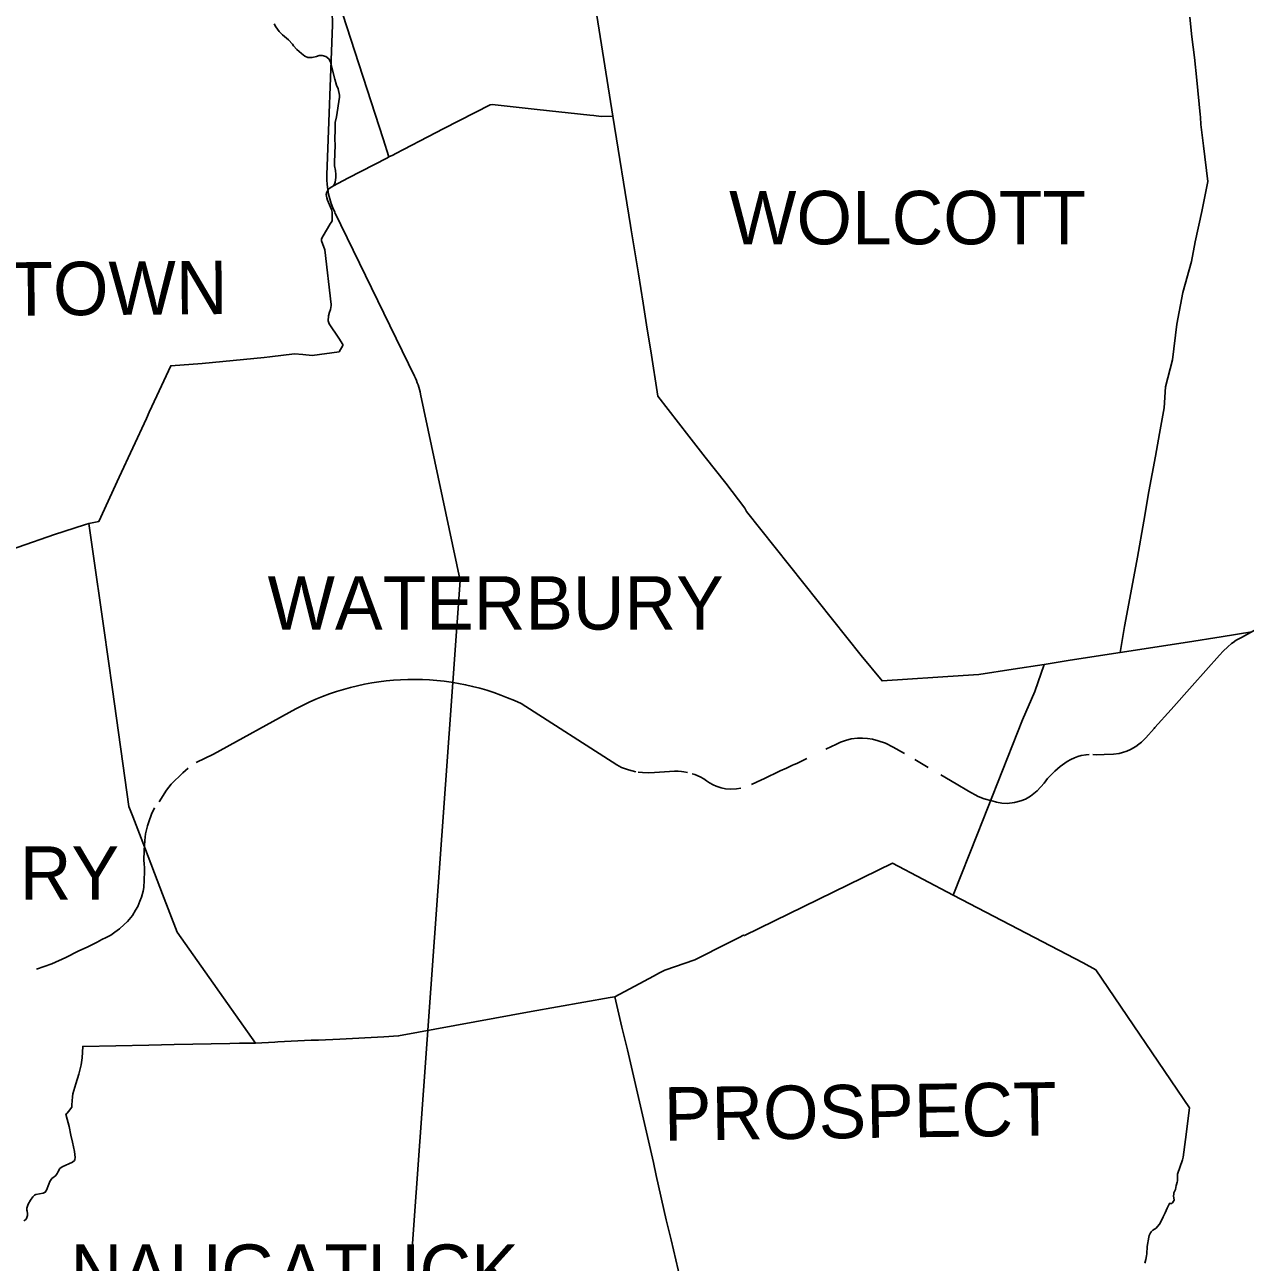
# Model space of a CAD drawing. Extents: x 0 to 2603, y -226 to 830.
# Drawn here: x 129.76 to 160.62, y 575 to 606.28 of the extents above; entities that cross this region are included whole.
import ezdxf

# ---------------------------------------------------------------- set-up
doc = ezdxf.new("R2010")
doc.units = 0
for name, color, linetype in [('CT_TSH_Map_Districts', 7, 'Continuous'), ('CT_TSH_Map_Interstate_Roads', 7, 'Continuous'), ('CT_TSH_Map_Town_Limits', 7, 'Continuous'), ('CT_TSH_Map_Town_Text', 7, 'Continuous'), ('CT_TSH_Map_US_and_State_Routes', 7, 'Continuous')]:
    doc.layers.add(name, color=color, linetype=linetype)

msp = doc.modelspace()

# ---------------------------------------------------------------- linework, layer by layer
at = {"layer": 'CT_TSH_Map_Districts'}
for points in [[(150.903, 609.889), (148.007, 607.903), (147.918, 607.835), (147.204, 607.367), (144.141, 607.01), (144.225, 606.511), (144.636, 603.968)], [(144.636, 603.968), (145.083, 601.204), (145.095, 601.095), (145.206, 600.434), (145.279, 599.977), (145.399, 599.241), (145.5, 598.58), (145.591, 598.037), (145.771, 596.887), (146.558, 595.88), (146.971, 595.343), (147.486, 594.686), (147.968, 594.058), (148.013, 593.97), (150.911, 590.334), (151.44, 589.692), (153.488, 589.831), (153.888, 589.851), (154.755, 589.988), (155.542, 590.106)], [(153.236, 584.273), (153.851, 585.821), (154.988, 588.704), (155.3, 589.426), (155.542, 590.106)], [(158.083, 574.97), (158.112, 575.066), (158.125, 575.154), (158.139, 575.205), (158.143, 575.393), (158.185, 575.631), (158.194, 575.671), (158.225, 575.736), (158.246, 575.763), (158.285, 575.803), (158.371, 575.857), (158.406, 575.901), (158.454, 575.962), (158.505, 576.051), (158.546, 576.145), (158.564, 576.177), (158.597, 576.249), (158.654, 576.362), (158.707, 576.482), (158.763, 576.484), (158.785, 576.498), (158.813, 576.54), (158.823, 576.564), (158.811, 576.676), (158.815, 576.717), (158.822, 576.753), (158.859, 576.838), (158.881, 576.933), (158.886, 576.964), (158.905, 577.02), (158.912, 577.054), (158.913, 577.151), (158.915, 577.219), (159.04, 577.585), (159.054, 577.65), (159.117, 578.102), (159.211, 578.896), (156.85, 582.386), (156.526, 582.564), (153.236, 584.273)]]:
    msp.add_lwpolyline(points, dxfattribs=at)
at = {"layer": 'CT_TSH_Map_Interstate_Roads'}
for points in [[(161.288, 591.209), (160.837, 590.96), (160.526, 590.791), (160.396, 590.717), (160.317, 590.663), (160.276, 590.633), (160.181, 590.55), (160.068, 590.439), (159.974, 590.34), (159.284, 589.568), (158.749, 588.969), (158.338, 588.511), (158.321, 588.489), (158.108, 588.253), (158.005, 588.145), (157.935, 588.088), (157.858, 588.034)], [(145.212, 587.395), (145.025, 587.441), (144.855, 587.506), (144.735, 587.569), (142.314, 589.116)], [(136.614, 588.984), (134.533, 587.841), (134.097, 587.632)], [(151.724, 588.015), (151.524, 588.114), (151.345, 588.179), (151.195, 588.215), (151.073, 588.235), (150.946, 588.244), (150.82, 588.244), (150.66, 588.223), (150.512, 588.183), (150.391, 588.142), (150.268, 588.085), (150.164, 588.03), (150.016, 587.965)], [(152.011, 587.854), (151.724, 588.015)], [(156.478, 587.801), (156.394, 587.782), (156.306, 587.749), (156.212, 587.707), (156.117, 587.652), (155.94, 587.523), (155.812, 587.409), (155.623, 587.225), (155.541, 587.109)], [(156.68, 587.829), (156.599, 587.824), (156.478, 587.801)], [(156.867, 587.822), (156.773, 587.83)], [(157.724, 587.957), (157.632, 587.915), (157.522, 587.88), (157.437, 587.858), (157.296, 587.839), (157.056, 587.827), (156.867, 587.822)], [(157.858, 588.034), (157.724, 587.957)], [(133.893, 587.482), (133.762, 587.367), (133.464, 587.077), (133.348, 586.927), (133.162, 586.637)], [(149.214, 587.575), (149.176, 587.563), (149.023, 587.488), (148.863, 587.421), (148.454, 587.219)], [(149.535, 587.731), (149.52, 587.724), (149.288, 587.605), (149.214, 587.575)], [(152.609, 587.502), (152.27, 587.7)], [(146.429, 587.391), (146.367, 587.4), (146.283, 587.405), (146.191, 587.406), (146.066, 587.401), (145.813, 587.387), (145.69, 587.375), (145.531, 587.37), (145.383, 587.376), (145.269, 587.386)], [(146.52, 587.372), (146.429, 587.391)], [(147.868, 586.983), (147.758, 586.962), (147.601, 586.955), (147.483, 586.963), (147.368, 586.986), (147.247, 587.028), (147.166, 587.064), (147.076, 587.113), (146.998, 587.162), (146.931, 587.216), (146.84, 587.266), (146.705, 587.322), (146.635, 587.343)], [(148.454, 587.219), (148.39, 587.188), (148.135, 587.071)], [(154.215, 586.657), (154.025, 586.706), (153.87, 586.765), (153.627, 586.901), (153.316, 587.086), (152.923, 587.317)], [(155.541, 587.109), (155.365, 586.909), (155.193, 586.775), (155.067, 586.704), (154.949, 586.659), (154.789, 586.617), (154.607, 586.595), (154.466, 586.602), (154.338, 586.624), (154.227, 586.656)], [(133.038, 586.482), (132.967, 586.324), (132.897, 586.128), (132.862, 586.026), (132.816, 585.821), (132.8, 585.66)], [(132.8, 585.66), (132.778, 585.402), (132.774, 585.158), (132.778, 585.064), (132.79, 584.963), (132.788, 584.871), (132.78, 584.652), (132.774, 584.469), (132.755, 584.375), (132.715, 584.228), (132.673, 584.127)], [(132.673, 584.127), (132.617, 583.986), (132.559, 583.892), (132.485, 583.764), (132.359, 583.606), (132.275, 583.532), (132.16, 583.426), (132.043, 583.339), (131.937, 583.263), (131.822, 583.204), (131.713, 583.152)], [(131.713, 583.152), (131.594, 583.09), (131.357, 582.966), (131.112, 582.858), (130.801, 582.7), (130.444, 582.542), (130.06, 582.403)]]:
    msp.add_lwpolyline(points, dxfattribs=at)
msp.add_arc((139.595, 583.395), 6.334, 64.576, 118.0692, dxfattribs=at)
at = {"layer": 'CT_TSH_Map_Town_Limits'}
for points in [[(138.331, 626.019), (137.723, 621.006), (137.355, 617.881), (137.077, 615.36), (136.757, 612.369), (136.636, 611.187), (136.553, 610.437), (136.656, 610.108), (136.665, 610.067), (137.111, 608.697), (137.489, 607.518), (137.807, 606.532), (138.825, 603.397), (138.97, 602.938)], [(150.903, 609.889), (148.007, 607.903), (147.918, 607.835), (147.204, 607.367), (144.141, 607.01), (144.225, 606.511), (144.636, 603.968)], [(136.067, 606.298), (136.11, 606.227), (136.196, 606.109), (136.275, 606.021), (136.428, 605.895), (136.533, 605.786), (136.556, 605.745), (136.642, 605.654), (136.758, 605.552), (136.846, 605.486), (136.918, 605.452), (136.957, 605.447), (137.03, 605.451), (137.139, 605.476), (137.208, 605.498), (137.286, 605.501), (137.372, 605.475), (137.411, 605.449), (137.458, 605.403), (137.496, 605.329), (137.599, 604.904), (137.646, 604.748), (137.684, 604.655), (137.722, 604.499), (137.721, 604.443), (137.642, 603.949), (137.614, 603.804), (137.608, 603.634), (137.603, 603.378), (137.609, 603.239), (137.591, 602.799), (137.597, 602.71), (137.623, 602.595), (137.63, 602.495), (137.626, 602.414), (137.612, 602.294), (137.584, 602.234), (137.567, 602.208)], [(159.224, 606.47), (159.277, 605.972), (159.339, 605.445), (159.397, 604.872), (159.481, 604.01), (159.493, 603.942), (159.505, 603.759), (159.572, 603.216), (159.676, 602.312), (159.525, 601.555), (159.36, 600.787), (159.267, 600.291), (159.043, 599.505), (158.897, 598.707), (158.787, 597.809), (158.606, 597.123), (158.577, 596.594), (158.454, 595.946), (158.351, 595.375), (158.188, 594.477), (158.058, 593.728), (157.899, 592.82), (157.706, 591.784), (157.573, 591.065), (157.462, 590.407)], [(144.636, 603.968), (144.338, 603.96), (144.154, 603.98), (144.052, 603.989), (142.718, 604.133), (142.647, 604.14), (141.584, 604.26), (141.527, 604.256), (140.355, 603.651), (139.953, 603.444), (139.338, 603.126), (139.145, 603.026), (139.071, 602.983), (138.97, 602.938)], [(144.636, 603.968), (145.083, 601.204), (145.095, 601.095), (145.206, 600.434), (145.279, 599.977), (145.399, 599.241), (145.5, 598.58), (145.591, 598.037), (145.771, 596.887), (146.558, 595.88), (146.971, 595.343), (147.486, 594.686), (147.968, 594.058), (148.013, 593.97), (150.911, 590.334), (151.44, 589.692), (153.488, 589.831), (153.888, 589.851), (154.755, 589.988), (155.542, 590.106)], [(137.567, 602.208), (137.935, 602.397), (138.934, 602.914), (138.97, 602.938)], [(131.381, 593.671), (131.638, 593.721), (132.149, 594.841), (132.838, 596.326), (132.908, 596.488), (133.104, 596.898), (133.453, 597.657), (134.25, 597.712), (135.814, 597.866), (135.958, 597.885), (136.585, 597.96), (136.796, 597.941), (137.026, 597.915), (137.71, 598.005), (137.805, 598.168), (137.801, 598.195), (137.702, 598.351), (137.456, 598.719), (137.435, 598.789), (137.439, 598.923), (137.464, 599.014), (137.489, 599.079), (137.511, 599.181), (137.511, 599.207), (137.351, 600.59), (137.264, 600.817), (137.262, 600.86), (137.285, 600.898), (137.42, 601.13), (137.484, 601.242), (137.507, 601.277), (137.531, 601.324), (137.539, 601.356), (137.532, 601.54), (137.515, 601.606), (137.416, 601.845), (137.399, 601.901), (137.386, 601.983), (137.399, 602.048), (137.44, 602.117), (137.486, 602.152), (137.567, 602.208)], [(131.381, 593.671), (131.27, 593.636), (130.51, 593.392), (127.748, 592.43), (127.364, 592.297), (126.832, 592.129), (125.938, 591.86), (124.766, 591.498), (124.644, 591.467), (122.487, 590.854), (122.296, 590.805)], [(131.381, 593.671), (131.47, 593.077), (131.762, 591.02), (131.976, 589.475), (132.397, 586.512), (132.496, 586.261), (132.744, 585.607), (133.247, 584.297), (133.619, 583.336), (135.597, 580.536)], [(160.795, 590.932), (160.016, 590.806), (159.167, 590.669), (157.462, 590.407)], [(155.542, 590.106), (156.201, 590.212), (157.462, 590.407)], [(153.236, 584.273), (153.851, 585.821), (154.988, 588.704), (155.3, 589.426), (155.542, 590.106)], [(144.684, 581.706), (144.921, 581.835), (145.189, 581.976), (145.657, 582.23), (145.815, 582.308), (145.944, 582.381), (146.704, 582.644), (147.553, 583.071), (147.83, 583.204), (147.936, 583.262), (147.965, 583.255), (151.704, 585.083), (153.236, 584.273)], [(158.083, 574.97), (158.112, 575.066), (158.125, 575.154), (158.139, 575.205), (158.143, 575.393), (158.185, 575.631), (158.194, 575.671), (158.225, 575.736), (158.246, 575.763), (158.285, 575.803), (158.371, 575.857), (158.406, 575.901), (158.454, 575.962), (158.505, 576.051), (158.546, 576.145), (158.564, 576.177), (158.597, 576.249), (158.654, 576.362), (158.707, 576.482), (158.763, 576.484), (158.785, 576.498), (158.813, 576.54), (158.823, 576.564), (158.811, 576.676), (158.815, 576.717), (158.822, 576.753), (158.859, 576.838), (158.881, 576.933), (158.886, 576.964), (158.905, 577.02), (158.912, 577.054), (158.913, 577.151), (158.915, 577.219), (159.04, 577.585), (159.054, 577.65), (159.117, 578.102), (159.211, 578.896), (156.85, 582.386), (156.526, 582.564), (153.236, 584.273)], [(135.597, 580.536), (136.083, 580.558), (136.158, 580.565), (137.004, 580.606), (137.192, 580.61), (137.728, 580.636), (138.841, 580.697), (139.214, 580.715), (142.563, 581.331), (144.562, 581.687), (144.684, 581.706)], [(147.644, 570.133), (147.042, 572.067), (146.578, 573.539), (146.106, 575.566), (145.985, 576.071), (145.73, 577.186), (145.659, 577.518), (144.999, 580.368), (144.858, 580.942), (144.684, 581.706)], [(135.597, 580.536), (135.419, 580.536), (135.367, 580.531), (135.188, 580.533), (134.946, 580.526), (133.543, 580.499), (132.896, 580.487), (131.226, 580.453), (131.215, 580.161), (131.186, 579.986), (131.132, 579.752), (131.052, 579.504), (131.031, 579.425), (130.975, 579.25), (130.965, 579.178), (130.951, 578.973), (130.95, 578.913), (130.867, 578.81), (130.831, 578.763), (130.803, 578.738), (130.835, 578.616), (130.883, 578.43), (130.925, 578.205), (130.968, 578.035), (131.021, 577.796), (131.035, 577.646), (131.029, 577.589), (131.019, 577.57), (130.966, 577.529), (130.707, 577.406), (130.652, 577.365), (130.594, 577.27), (130.582, 577.239), (130.564, 577.215), (130.541, 577.183), (130.45, 577.113), (130.396, 577.037), (130.366, 576.969), (130.31, 576.819), (130.279, 576.767), (130.258, 576.756), (130.226, 576.744), (130.042, 576.711), (130.008, 576.695), (129.968, 576.651), (129.907, 576.562), (129.85, 576.462), (129.816, 576.359), (129.814, 576.312), (129.821, 576.29), (129.834, 576.23), (129.833, 576.179), (129.818, 576.152), (129.803, 576.104), (129.785, 576.079), (129.742, 576.04)]]:
    msp.add_lwpolyline(points, dxfattribs=at)
at = {"layer": 'CT_TSH_Map_US_and_State_Routes'}
for p, q in [((137.54, 606.277), (137.404, 602.481)), ((137.603, 601.535), (139.614, 597.396)), ((139.772, 596.937), (140.77, 592.227))]:
    msp.add_line(p, q, dxfattribs=at)
msp.add_lwpolyline([(140.77, 592.227), (139.566, 575.467), (139.123, 571.38)], dxfattribs=at)
for centre, start, end in [((135.541, 606.349), 357.945, 49.9585), ((139.402, 602.409), 177.945, 205.9065), ((137.815, 596.522), 11.967, 25.9065)]:
    msp.add_arc(centre, 2, start, end, dxfattribs=at)

# ---------------------------------------------------------------- texts
at = {"layer": 'CT_TSH_Map_Town_Text'}
for s, p in [('WOLCOTT', (147.572, 600.727)), ('MIDDLEBURY', (120.31, 584.158)), ('NAUGATUCK', (130.917, 574.095))]:
    msp.add_text(s, height=1.35, dxfattribs=at).set_placement(p)
for s, rotation, p in [('WATERTOWN', 0.4245, (122.859, 598.874)), ('WATERBURY', 360, (135.902, 590.988)), ('PROSPECT', 0.7655, (145.931, 578.069))]:
    msp.add_text(s, height=1.35, rotation=rotation, dxfattribs=at).set_placement(p)

doc.saveas('drawing.dxf')
